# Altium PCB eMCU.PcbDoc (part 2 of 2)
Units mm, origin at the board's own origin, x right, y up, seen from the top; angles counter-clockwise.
Board outline 90 x 58 mm, 2 copper layers (Top Layer, Bottom Layer); 104 components, 112 nets, 449 pads, 70 vias.
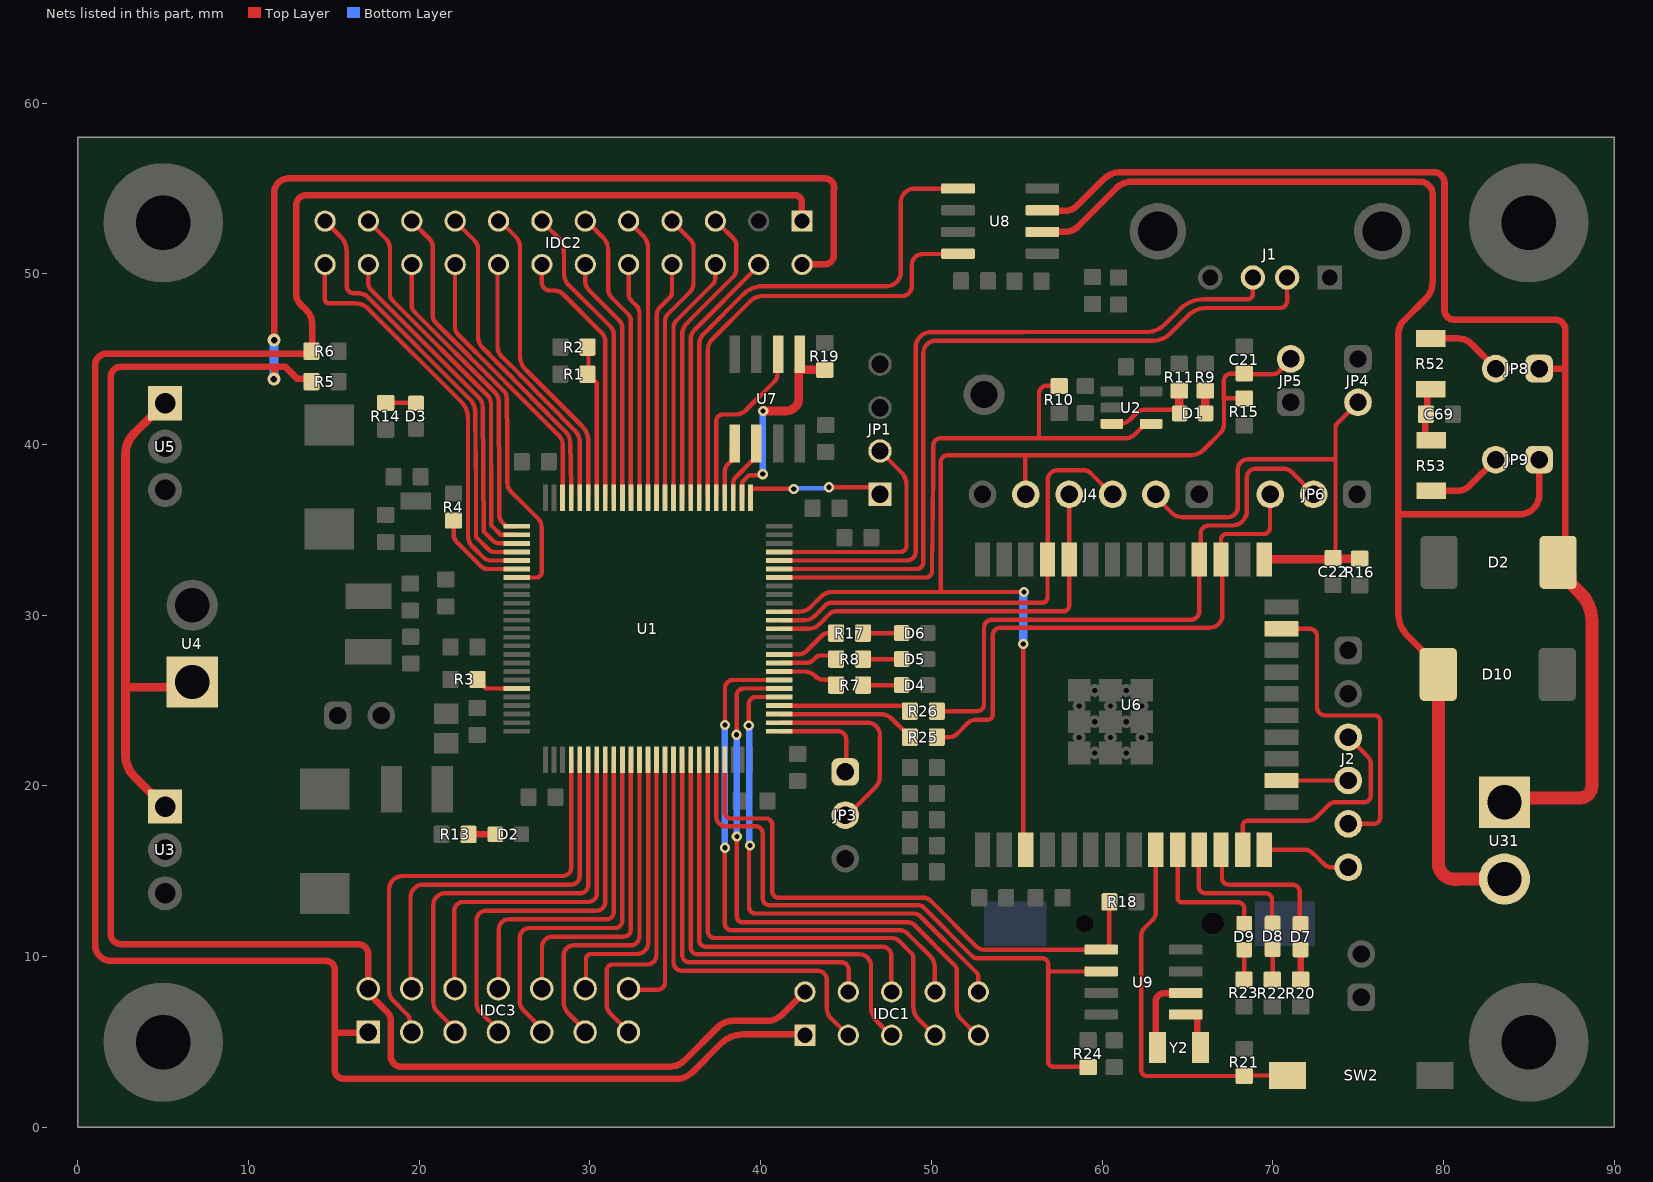
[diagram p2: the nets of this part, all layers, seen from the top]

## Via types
v1: diameter 0.6, hole 0.3, Top Layer to Bottom Layer, tented both sides, 59 vias
v2: diameter 0.762, hole 0.381, Top Layer to Bottom Layer, tented both sides, 11 vias

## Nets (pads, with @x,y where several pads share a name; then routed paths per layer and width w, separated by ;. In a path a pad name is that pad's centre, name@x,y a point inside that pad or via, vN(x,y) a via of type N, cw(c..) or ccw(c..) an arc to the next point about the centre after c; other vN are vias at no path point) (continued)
NetC21_2: C21.2 J4.5 JP5.2 R15.1 U1.65 U6.3 | length 65.8
  Top Layer w0.254: U1.65@41.081,30.21 42.274,30.21 ccw(c42.274,31.132) 42.925,30.479 ; 42.926,30.48 43.532,31.086 cw(c44.196,30.422) 44.196,31.361 50.681,31.361 ; v1(55.384,28.322) 55.384,16.413 U6.3@55.532,16.266 ; v1(55.425,31.361) 50.681,31.361 ; J4.5@55.534,37.084 55.505,37.113 55.505,39.37 ; 65.952,39.695 cw(c65.166,40.481) 65.166,39.37 55.505,39.37 ; 65.953,39.695 66.9,40.642 ccw(c66.331,41.212) 67.136,41.212 67.136,42.71 ; 67.126,42.71 67.126,43.737 cw(c67.538,43.737) 67.538,44.149 68.307,44.149 C21.2@68.326,44.168 68.369,44.125 69.985,44.125 ccw(c69.986,44.681) 70.38,44.288 71.044,44.952 JP5.2@71.044,45.015 ; 67.152,42.71 R15.1@68.316,42.71 ; 50.681,31.361 50.62,31.422 50.546,31.496 50.546,38.971 cw(c50.945,38.971) 50.945,39.37 55.505,39.37
  Bottom Layer w0.508: v1(55.384,28.322) 55.384,31.295 55.425,31.336 v1(55.425,31.361)
NetC22_2: C22.2 J4.2 JP4.2 R16.1 U6.25 | length 29.5
  Top Layer w0.254: J4.2@63.154,37.084 63.154,36.922 64.059,36.017 ccw(c64.714,36.673) 64.714,35.746 67.357,35.746 ccw(c67.357,36.341) 67.952,36.341 67.952,38.552 cw(c68.531,38.552) 68.531,39.13 73.67,39.13 ; U6.25@69.502,33.266 U6.25@69.51,33.274 ; C22.2@73.324,33.274 73.67,33.62 73.67,39.13 ; JP4.2@74.987,42.451 73.865,41.328 ccw(c74.167,40.933) 73.67,40.931 73.67,40.489 73.67,39.13 ; R16.1@75.077,33.315 R16.1@75.083,33.321
  Top Layer w0.508: U6.25@69.51,33.274 C22.2@73.324,33.274 ; C22.2@73.298,33.315 R16.1@75.077,33.315
NetC69_2: C69.2 R52.1 R53.2 | length 3
  Top Layer w0.381: R53.2@78.737,40.206 78.935,40.404 78.935,41.746 C69.2@78.963,41.774 ; C69.2@79.054,42.028 79.054,43.042 R52.1@79.262,43.25
NetD1_A: D1.A R9.1 | length 1.5
  Top Layer w0.508: D1.A@66.04,41.658 R9.1@66.04,43.152
NetD1_C: D1.C R11.1 U2.3 | length 5.6
  Top Layer w0.254: U2.3@60.577,41.214 61.012,41.214 ccw(c61.012,42.123) 61.457,41.331 ccw(c61.012,42.123) 61.636,41.463 ccw(c61.012,42.123) 61.654,41.48 62.007,41.833 cw(c62.521,41.319) 62.521,42.046 ; 62.522,42.046 64.505,42.046 64.547,42.005 D1.C@64.547,41.821
  Top Layer w0.508: D1.C@64.516,42.005 R11.1@64.516,43.152
NetD2_2: D2.2 JP8.1 U8.7 U31.1 | length 74
  Top Layer w0.381: U8.7@56.5,53.721 U8.7@56.545,53.766 ; U8.7@57.276,53.698 57.866,53.698 ccw(c57.866,54.601) 58.482,53.94 ccw(c57.866,54.601) 58.505,53.962 ; 58.504,53.963 60.05,55.509 cw(c61.139,54.42) 61.139,55.96 79.422,55.96 cw(c79.422,55.326) 80.056,55.326 80.056,47.865 ccw(c80.602,47.865) 80.602,47.319 86.542,47.319 cw(c86.542,46.739) 87.122,46.739 87.122,44.45 ; JP8.1@85.598,44.45 87.122,44.45 ; D2.2@86.71,33.095 87.122,33.507 87.122,44.45
  Top Layer w0.762: U31.1@83.566,19.05 83.82,19.304 88.011,19.304 ccw(c88.011,19.976) 88.683,19.976 88.683,29.691 ccw(c86.431,29.691) 88.024,31.282 ; D2.2@86.71,33.095 87.419,32.386 87.419,31.888 88.023,31.283
NetD2_A: D2.A R13.1 | length 1.6
  Top Layer w0.381: R13.1@22.892,17.162 24.402,17.162 D2.A@24.47,17.094
NetD3_A: D3.A R14.1 | length 2.1
  Top Layer w0.254: R14.1@18.034,42.446 D3.A@20.094,42.446
NetD4_A: D4.A R7.1 | length 2.8
  Top Layer w0.254: R7.1@46.002,25.908 D4.A@48.514,25.908 ; D4.A@48.26,25.908 D4.A@48.26,26.162
NetD5_A: D5.A R8.1 | length 3
  Top Layer w0.254: R8.1@46.171,27.601 R8.1@46.002,27.432 D5.A@48.514,27.432 ; D5.A@48.119,27.686 D5.A@48.288,27.517
NetD6_A: D6.A R17.1 | length 2.8
  Top Layer w0.254: R17.1@46.002,28.956 D6.A@48.514,28.956 ; D6.A@48.26,28.956 D6.A@48.26,29.21
NetD7_A: D7.A R20.1 | length 1.7
  Top Layer w0.381: R20.1@71.628,8.664 D7.A@71.628,10.414
NetD7_C: D7.C U6.12 | length 8.6
  Top Layer w0.254: U6.12@66.962,16.266 67.02,16.207 67.02,14.604 ccw(c67.4,14.604) 67.4,14.224 71.133,14.224 cw(c71.133,13.769) 71.579,13.859 cw(c71.133,13.769) 71.588,13.769 71.588,13.708 ; 71.579,13.708 71.579,11.983 D7.C@71.628,11.934
NetD8_A: D8.A R22.1 | length 1.8
  Top Layer w0.254: R22.1@69.967,8.66 69.989,8.682 D8.A@69.989,10.433
NetD8_C: D8.C U6.11 | length 8.3
  Top Layer w0.254: U6.11@65.692,16.266 65.666,16.24 65.666,14.097 ccw(c66.047,14.097) 66.047,13.716 69.596,13.716 cw(c69.596,13.364) 69.948,13.364 69.948,13.259 ; 69.951,13.259 69.951,11.991 D8.C@69.989,11.953
NetD9_A: D9.A R23.1 | length 1.8
  Top Layer w0.254: R23.1@68.312,8.667 68.326,8.681 D9.A@68.326,10.416
NetD9_C: D9.C U6.10 | length 8
  Top Layer w0.254: U6.10@64.422,16.266 64.422,13.455 ccw(c64.688,13.455) 64.688,13.188 ; 64.688,13.183 67.97,13.183 cw(c67.97,12.827) 68.326,12.827 D9.C@68.326,11.936
NetD10_2: D10.2 JP9.1 U8.6 U31.2 | length 80.1
  Top Layer w0.381: U8.6@56.5,52.451 57.805,52.451 ccw(c57.805,53.578) 58.521,52.708 ccw(c57.805,53.578) 58.602,52.781 ; 58.598,52.785 60.831,55.018 ; 60.83,55.02 cw(c61.751,54.099) 60.881,55.067 cw(c61.751,54.099) 61.751,55.401 78.605,55.401 cw(c78.605,54.643) 79.361,54.696 cw(c78.605,54.643) 79.363,54.643 ; 77.35,46.427 77.35,35.907 ; 77.359,46.427 77.359,46.512 cw(c78.399,46.512) 77.663,47.248 78.972,48.556 ccw(c78.034,49.494) 79.361,49.494 79.361,54.643 ; D10.2@79.692,27.003 77.891,28.804 77.889,28.806 cw(c79.19,30.107) 77.35,30.107 77.35,30.108 77.35,35.907 ; JP9.1@85.613,38.608 85.613,37.086 cw(c84.434,37.086) 84.434,35.907 77.35,35.907
  Top Layer w0.635: D10.2@79.692,26.533 D10.2@79.692,27.003
  Top Layer w0.762: D10.2@79.692,26.533 79.692,15.494 ccw(c80.648,15.494) 80.495,14.55 ccw(c80.648,15.494) 80.648,14.538 80.862,14.538 ; 80.862,14.55 U31.2@83.566,14.55
NetIDC1_1: IDC1.1 IDC2.1 IDC3.1 R6.2 | length 138.4
  Top Layer w0.381: 13.024,48.235 13.444,47.816 ; 13.026,48.237 cw(c13.58,48.791) 12.797,48.791 12.797,54.013 cw(c13.394,54.013) 13.394,54.61 41.987,54.61 cw(c41.987,54.179) 42.418,54.179 IDC2.1@42.418,53.086 ; 13.444,47.816 cw(c12.78,47.153) 13.718,47.153 13.718,47.122 ; R6.2@13.688,45.466 13.537,45.315 1.678,45.315 ccw(c1.678,44.654) 1.016,44.654 1.016,10.702 ccw(c1.965,10.702) 1.965,9.753 14.546,9.753 cw(c14.546,9.247) 15.052,9.247 ; R6.2@13.688,45.72 13.725,45.757 13.725,47.122 ; 15.061,9.247 15.061,5.545 ; 15.572,2.845 35.036,2.845 ccw(c35.036,4.232) 36.017,3.251 37.669,4.903 cw(c39.001,3.572) 39.001,5.455 42.412,5.455 IDC1.1@42.472,5.394 ; 15.572,2.849 cw(c15.572,3.359) 15.061,3.359 15.061,5.545 ; IDC3.1@17.018,5.588 16.975,5.545 15.061,5.545
NetIDC1_2: IDC1.2 IDC2.2 IDC3.2 R5.2 | length 144.3
  Top Layer w0.381: v2(11.493,43.827) 11.523,43.857 11.523,44.325 ; v2(11.502,46.12) 11.514,46.132 11.514,54.708 ccw(c11.133,54.708) 11.514,54.724 cw(c12.337,54.763) 12.337,55.587 43.764,55.587 cw(c43.764,55.041) 44.296,54.916 44.296,51.105 cw(c43.915,51.105) 44.294,51.075 cw(c43.722,51.121) 43.72,50.546 IDC2.2@42.672,50.546 ; 12.119,44.551 12.119,44.548 11.74,44.548 2.526,44.548 ccw(c2.526,43.955) 1.933,43.955 1.933,11.328 ccw(c2.516,11.328) 2.516,10.744 16.408,10.744 cw(c16.408,10.134) 17.018,10.131 IDC3.2@17.018,8.128 ; 12.165,44.546 12.87,43.841 13.535,43.841 R5.2@13.688,43.688 ; IDC3.2@17.207,8.063 17.207,7.683 18.132,6.759 cw(c17.626,6.253) 18.338,6.324 cw(c17.626,6.253) 18.341,6.253 ; 18.338,6.253 18.338,4.169 ccw(c18.95,4.169) 18.95,3.556 34.671,3.556 ccw(c34.671,4.77) 35.529,3.912 ; 35.531,3.909 37.531,5.909 ; 37.535,5.905 cw(c38.339,5.101) 38.339,6.238 40.346,6.238 ccw(c40.346,7.553) 41.277,6.624 IDC1.2@42.596,7.943
  Bottom Layer w0.508: v2(11.493,43.827) 11.497,43.831 11.497,46.115 v2(11.502,46.12)
NetIDC1_3: IDC1.3 U1.41 | length 24.8
  Top Layer w0.254: U1.41@34.901,21.423 34.901,9.643 ccw(c35.358,9.643) 35.358,9.186 43.324,9.186 cw(c43.324,8.635) 43.874,8.635 43.874,6.981 ccw(c44.683,6.981) 44.058,6.468 ccw(c44.683,6.981) 44.111,6.409 ; 44.124,6.402 IDC1.3@44.938,5.588
NetIDC1_4: IDC1.4 U1.42 | length 23
  Top Layer w0.254: U1.42@35.401,21.53 35.401,10.109 ccw(c35.833,10.109) 35.833,9.678 44.724,9.678 cw(c44.724,9.248) 45.154,9.248 IDC1.4@45.154,7.96
NetIDC1_5: IDC1.5 U1.43 | length 26.4
  Top Layer w0.254: U1.43@35.903,21.528 35.903,10.536 ccw(c36.299,10.536) 36.299,10.141 45.785,10.141 cw(c45.785,9.459) 46.467,9.459 46.467,7.102 ; 46.467,7.101 ccw(c47.786,7.101) 46.854,6.167 47.433,5.588 IDC1.5@47.498,5.588
NetIDC1_6: IDC1.6 U1.44 | length 24.4
  Top Layer w0.254: U1.44@36.401,21.53 36.401,11.044 cw(c36.147,11.044) 36.4,11.018 ccw(c36.788,10.976) 36.789,10.586 47.11,10.586 cw(c47.11,10.038) 47.659,10.038 IDC1.6@47.659,7.96
NetIDC1_7: IDC1.7 U1.45 | length 27.8
  Top Layer w0.254: U1.45@36.901,21.53 36.901,11.5 ccw(c37.304,11.5) 37.304,11.096 47.675,11.096 cw(c47.675,10.458) 48.124,10.911 cw(c47.675,10.458) 48.126,10.909 48.84,10.195 cw(c48.587,9.943) 48.944,9.943 ; 48.946,7.068 ccw(c50,7.068) 49.256,6.322 49.502,6.075 50.092,5.485 IDC1.7@50.092,5.394 ; 48.946,7.07 48.946,9.943
NetIDC1_8: IDC1.8 U1.57 | length 32.3
  Top Layer w0.254: 37.902,11.949 ccw(c38.305,11.949) 38.356,11.548 cw(c38.387,11.296) 38.387,11.55 48.123,11.55 cw(c48.123,10.851) 48.618,11.346 48.628,11.335 ; 37.902,11.95 37.902,16.378 v1(37.908,16.384) ; v1(37.913,23.578) 37.91,23.581 37.91,25.671 ccw(c37.656,25.671) 37.91,25.689 cw(c38.391,25.727) 38.391,26.21 U1.57@41.081,26.21 ; 48.631,11.338 49.931,10.038 ; 49.931,10.037 cw(c49.296,9.4) 50.196,9.4 50.196,7.963 IDC1.8@50.216,7.943
  Bottom Layer w0.254: v1(37.908,16.384) v1@37.911,16.387 ; v1@37.911,23.576 v1(37.913,23.578)
  Bottom Layer w0.381: v1@37.911,16.387 v1@37.911,23.576
NetIDC1_9: IDC1.9 U1.56 | length 34.2
  Top Layer w0.254: v1(38.593,23.001) 38.593,25.209 ccw(c38.339,25.209) 38.591,25.239 cw(c39.008,25.29) 39.008,25.71 U1.56@41.081,25.71 ; v1(38.608,17.04) 38.608,12.335 ccw(c38.92,12.335) 38.92,12.023 48.609,12.023 cw(c48.609,11.48) 48.994,11.864 ; 48.997,11.868 51.375,9.49 cw(c51.087,9.202) 51.494,9.226 51.494,6.891 ; 51.494,6.89 ccw(c52.215,6.89) 51.706,6.38 ; 51.706,6.379 52.632,5.453 IDC1.9@52.632,5.394
  Bottom Layer w0.254: v1(38.593,23.001) v1@38.6,22.994 ; v1@38.6,17.048 v1(38.608,17.04)
  Bottom Layer w0.381: v1@38.6,17.048 v1@38.6,22.994
NetIDC1_10: IDC1.10 U1.55 | length 30
  Top Layer w0.254: v1(39.305,23.541) 39.305,24.782 ccw(c39.051,24.782) 39.305,24.789 cw(c39.712,24.803) 39.712,25.21 U1.55@41.081,25.21 ; v1(39.37,16.51) 39.32,16.46 39.32,12.904 ccw(c39.689,12.902) 39.691,12.533 48.968,12.533 cw(c48.969,12.002) 49.345,12.377 52.359,9.363 52.643,9.079 cw(c52.404,8.838) 52.744,8.838 IDC1.10@52.744,7.955
  Bottom Layer w0.254: v1(39.305,23.541) v1@39.337,23.508 ; v1@39.337,16.543 v1(39.37,16.51)
  Bottom Layer w0.381: v1@39.337,16.543 v1@39.337,23.508
NetIDC2_4: IDC2.4 U1.83 | length 15.1
  Top Layer w0.254: U1.83@35.901,36.89 35.901,46.08 ccw(c35.647,46.08) 35.901,46.095 cw(c36.716,46.149) 36.139,46.727 39.703,50.292 IDC2.4@39.87,50.292
NetIDC2_5: IDC2.5 U1.84 | length 17.8
  Top Layer w0.254: U1.84@35.401,36.89 35.401,46.362 ccw(c35.147,46.362) 35.401,46.372 cw(c36.398,46.416) 35.692,47.122 38.381,49.811 ccw(c37.916,50.277) 38.575,50.277 38.575,51.646 38.575,51.689 ccw(c38.067,51.689) 38.575,51.706 ccw(c38.067,51.689) 38.426,52.048 37.592,52.882 IDC2.5@37.592,53.086
NetIDC2_6: IDC2.6 U1.85 | length 14.6
  Top Layer w0.254: U1.85@34.901,36.89 34.901,37.543 34.901,46.882 cw(c35.41,46.882) 35.05,47.242 37.205,49.397 ccw(c36.889,49.713) 37.336,49.713 ; 37.338,49.713 IDC2.6@37.338,50.546
NetIDC2_7: IDC2.7 U1.86 | length 17.2
  Top Layer w0.254: U1.86@34.401,36.89 34.402,47.27 ; 34.403,47.27 cw(c34.888,47.27) 34.544,47.613 ; 34.545,47.613 35.838,48.907 ccw(c35.285,49.461) 36.068,49.461 ; IDC2.7@34.883,53.001 35.887,51.997 ; 35.887,51.997 cw(c35.449,51.558) 36.068,51.522 ccw(c36.322,51.509) 36.068,51.51 36.068,49.462
NetIDC2_8: IDC2.8 U1.87 | length 14
  Top Layer w0.254: U1.87@33.901,36.89 33.914,36.903 33.914,37.638 33.921,37.645 33.921,47.617 ; 33.921,47.618 cw(c34.495,47.618) 34.089,48.023 34.673,48.607 ccw(c34.346,48.934) 34.808,48.934 IDC2.8@34.808,50.546
NetIDC2_9: IDC2.9 U1.88 | length 16.6
  Top Layer w0.254: IDC2.9@32.258,53.086 33.115,52.229 cw(c32.429,51.543) 33.399,51.543 ; U1.88@33.401,36.89 33.401,51.543
NetIDC2_10: IDC2.10 U1.89 | length 13.9
  Top Layer w0.254: IDC2.10@32.268,50.546 32.268,48.79 ccw(c32.758,48.79) 32.412,48.444 32.708,48.148 32.74,48.116 cw(c32.35,47.726) 32.901,47.742 cw(c32.35,47.726) 32.901,47.726 U1.89@32.901,36.89
NetIDC2_11: IDC2.11 U1.90 | length 17.1
  Top Layer w0.254: IDC2.11@29.972,53.086 29.972,52.929 30.757,52.143 ; 30.758,52.142 cw(c30.006,51.39) 31.068,51.332 ccw(c31.322,51.32) 31.068,51.321 31.068,49.137 ccw(c31.863,49.137) 31.301,48.575 32.232,47.644 cw(c31.821,47.234) 32.401,47.261 cw(c31.821,47.234) 32.402,47.234 U1.90@32.401,36.89
NetIDC2_12: IDC2.12 U1.91 | length 14.5
  Top Layer w0.254: IDC2.12@29.728,50.546 29.728,49.579 ccw(c30.486,49.579) 29.932,49.062 ccw(c30.486,49.579) 29.95,49.043 ; 29.951,49.043 31.692,47.302 cw(c31.189,46.799) 31.9,46.799 31.9,46.772 ; U1.91@31.901,36.89 31.901,46.772 31.903,46.771
NetIDC2_13: IDC2.13 U1.92 | length 17.7
  Top Layer w0.254: IDC2.13@27.432,53.086 27.432,52.832 28.2,52.064 cw(c27.543,51.401) 28.476,51.4 28.476,51.188 ; 28.485,51.188 28.485,50.021 ccw(c29.458,50.021) 28.71,49.398 ccw(c29.458,50.021) 28.77,49.332 ; 28.773,49.335 31.227,46.881 ; 31.228,46.88 cw(c30.813,46.464) 31.401,46.464 ; U1.92@31.401,36.89 31.401,46.463
NetIDC2_14: IDC2.14 U1.93 | length 15.1
  Top Layer w0.254: IDC2.14@27.178,50.292 27.188,50.282 27.188,49.492 ccw(c27.659,49.492) 27.628,49.023 ; 27.686,49.023 27.901,49.023 cw(c27.901,48.286) 28.422,48.807 ; 28.492,48.742 30.694,46.54 cw(c30.188,46.03) 30.899,46.133 cw(c30.647,46.098) 30.901,46.098 U1.93@30.901,36.89
NetIDC2_15: IDC2.15 U1.95 | length 18.3
  Top Layer w0.254: IDC2.15@24.638,53.086 24.742,53.086 25.64,52.188 cw(c25,51.548) 25.905,51.548 ; 25.908,51.548 25.908,45.195 25.908,45.193 ccw(c27.089,45.193) 26.264,44.348 cw(c26.086,44.167) 26.266,44.346 29.546,41.066 cw(c28.701,40.211) 29.901,40.153 ccw(c30.155,40.142) 29.901,40.143 ; U1.95@29.901,36.89 29.901,37.543 29.901,40.142
NetIDC2_16: IDC2.16 U1.96 | length 15.6
  Top Layer w0.254: 24.586,46.385 24.586,50.494 IDC2.16@24.638,50.546 ; 24.589,45.738 ccw(c25.416,45.738) 24.932,45.068 24.944,45.056 ; 24.589,45.739 24.589,46.385 ; 24.945,45.055 25.814,44.186 25.844,44.156 25.844,44.151 29.136,40.8 29.138,40.797 cw(c28.495,40.158) 29.401,40.118 ccw(c29.655,40.108) 29.401,40.11 ; U1.96@29.401,36.89 29.401,37.543 29.401,40.108
NetIDC2_17: IDC2.17 U1.97 | length 18.9
  Top Layer w0.254: IDC2.17@22.098,53.086 23.234,51.95 cw(c22.717,51.433) 23.446,51.496 23.446,46.316 ccw(c24.348,46.316) 23.69,45.699 24.519,44.856 ccw(c25.416,45.738) 24.521,44.854 28.585,40.74 cw(c27.956,40.111) 28.846,40.113 cw(c27.956,40.111) 28.846,40.111 28.9,37.543 U1.97@28.913,36.903
NetIDC2_18: IDC2.18 U1.98 | length 16.2
  Top Layer w0.254: 22.098,46.874 ccw(c22.725,46.874) 22.282,46.43 ; 22.098,46.875 IDC2.18@22.098,50.546 ; 22.283,46.429 24.466,44.246 25.557,43.155 28.103,40.604 cw(c27.601,39.979) 28.403,39.979 U1.98@28.403,36.892
NetIDC2_19: IDC2.19 U1.7 | length 25.2
  Top Layer w0.254: IDC2.19@19.558,53.086 20.59,52.054 ; 20.591,52.056 cw(c20.095,51.559) 20.629,52.015 cw(c20.095,51.559) 20.797,51.559 20.797,47.542 20.797,47.54 ccw(c21.366,47.54) 20.965,47.137 20.966,47.135 24.957,43.144 cw(c24.552,42.739) 25.125,42.739 25.125,42.586 ; 25.125,42.563 25.162,40.48 25.162,37.754 25.162,37.753 ccw(c25.865,37.753) 25.367,37.256 25.369,37.254 26.195,36.429 26.958,35.665 cw(c26.426,35.134) 27.178,35.148 cw(c26.426,35.134) 27.178,35.134 27.178,35.116 27.178,32.533 cw(c26.857,32.533) 26.857,32.212 U1.7@25.723,32.212
NetIDC2_20: IDC2.20 U1.1 | length 18.2
  Top Layer w0.254: 19.558,48.173 ccw(c20.138,48.173) 19.731,47.759 24.423,43.068 ; 19.558,48.174 IDC2.20@19.558,50.546 ; 24.423,43.067 cw(c23.862,42.505) 24.655,42.454 ccw(c24.909,42.439) 24.655,42.44 ; 24.655,42.439 24.655,42.309 24.655,42.307 24.69,37.398 24.69,35.893 ccw(c25.346,35.892) 24.883,35.427 25.068,35.242 25.068,35.223 25.081,35.21 U1.1@25.721,35.21
NetIDC2_21: IDC2.21 U1.2 | length 22.4
  Top Layer w0.254: IDC2.21@17.018,53.086 18.034,52.07 cw(c17.421,51.457) 18.288,51.457 18.288,48.814 ccw(c18.823,48.814) 18.446,48.434 23.989,42.891 cw(c23.461,42.36) 23.99,42.89 cw(c23.461,42.36) 24.21,42.354 ; 24.21,42.353 24.218,35.274 24.292,35.2 24.778,34.714 25.244,34.714 25.248,34.71 U1.2@25.721,34.71
NetIDC2_22: IDC2.22 U1.3 | length 20.3
  Top Layer w0.254: IDC2.22@17.018,50.292 17.018,49.449 ccw(c17.56,49.449) 17.147,49.098 ccw(c17.56,49.449) 17.177,49.066 ; 17.178,49.067 23.213,43.033 23.492,42.753 ; 23.493,42.752 cw(c22.938,42.199) 23.722,42.202 cw(c22.938,42.199) 23.722,42.199 23.722,42.191 23.729,42.118 ; 23.729,42.117 23.785,34.904 23.859,34.83 24.247,34.442 24.248,34.444 24.273,34.419 24.339,34.353 ccw(c24.673,34.688) 24.673,34.215 U1.3@25.716,34.215
NetIDC2_23: IDC2.23 U1.4 | length 25.2
  Top Layer w0.254: IDC2.23@14.486,53.086 15.401,52.171 cw(c14.562,51.332) 15.748,51.332 15.748,49.276 ccw(c16.172,49.276) 16.172,48.852 16.47,48.852 ; 16.47,48.853 cw(c16.47,48.133) 16.509,48.852 cw(c16.47,48.133) 16.979,48.643 ; 16.979,48.642 17.082,48.54 22.893,42.729 22.899,42.722 cw(c22.16,41.866) 23.292,41.866 23.329,37.358 cw(c23.075,37.356) 23.329,37.356 23.329,34.583 24.074,33.838 ccw(c24.382,34.145) 24.382,33.71 U1.4@25.721,33.71
NetIDC2_24: IDC2.24 U1.5 | length 23.8
  Top Layer w0.254: 14.469,48.514 IDC2.24@14.469,50.301 ; 14.478,48.514 ccw(c14.725,48.514) 14.725,48.267 16.284,48.267 ; 16.285,48.267 cw(c16.285,47.268) 16.992,47.974 ; 16.993,47.973 22.445,42.521 22.448,42.521 cw(c21.459,41.528) 22.86,41.471 22.86,34.651 ccw(c23.721,34.651) 23.113,34.041 23.229,33.926 ; 23.226,33.924 23.794,33.356 ccw(c24.147,33.71) 24.147,33.21 U1.5@25.721,33.21
NetIDC3_3: IDC3.3 U1.29 | length 26.6
  Top Layer w0.254: 19.439,6.29 19.439,5.707 IDC3.3@19.558,5.588 ; 19.44,6.29 ccw(c19.009,6.29) 19.439,6.313 ccw(c19.009,6.29) 19.314,6.594 18.461,7.447 cw(c19.011,7.998) 18.233,7.998 18.233,13.928 cw(c19.037,13.928) 19.037,14.732 28.421,14.732 ccw(c28.421,15.212) 28.901,15.212 U1.29@28.901,21.53
NetIDC3_4: IDC3.4 U1.30 | length 22.8
  Top Layer w0.254: IDC3.4@19.558,8.128 19.495,8.191 19.495,13.441 ccw(c19.241,13.441) 19.495,13.45 cw(c20.238,13.48) 20.238,14.224 28.894,14.224 ccw(c28.894,14.731) 29.401,14.731 U1.30@29.401,21.53
NetIDC3_5: IDC3.5 U1.31 | length 25
  Top Layer w0.254: 20.829,7.331 ccw(c21.589,7.331) 21.053,6.793 ; 20.829,7.332 20.829,13.031 cw(c21.514,13.031) 21.514,13.716 29.409,13.716 ccw(c29.409,14.208) 29.901,14.208 U1.31@29.901,21.53 ; 21.053,6.792 22.098,5.747 IDC3.5@22.098,5.588
NetIDC3_6: IDC3.6 U1.32 | length 21.3
  Top Layer w0.254: IDC3.6@22.098,8.128 22.055,8.171 22.055,12.687 cw(c22.577,12.687) 22.577,13.208 29.911,13.208 ccw(c29.911,13.698) 30.4,13.698 U1.32@30.401,21.53
NetIDC3_7: IDC3.7 U1.33 | length 23.5
  Top Layer w0.254: 23.354,7.261 ccw(c24.023,7.261) 23.551,6.787 24.638,5.7 IDC3.7@24.638,5.588 ; 23.354,7.262 23.354,12.123 cw(c23.931,12.123) 23.931,12.7 30.39,12.7 ccw(c30.39,13.211) 30.901,13.211 U1.33@30.901,21.53
NetIDC3_8: IDC3.8 U1.34 | length 19.7
  Top Layer w0.254: IDC3.8@24.638,8.128 24.67,8.16 24.67,11.613 cw(c25.249,11.613) 25.249,12.192 30.987,12.192 ccw(c30.987,12.606) 31.401,12.606 U1.34@31.401,21.53
NetIDC3_9: IDC3.9 U1.35 | length 22
  Top Layer w0.254: 25.887,7.412 ccw(c26.664,7.412) 26.116,6.862 27.178,5.8 IDC3.9@27.178,5.588 ; 25.887,7.413 25.887,11.092 cw(c26.479,11.092) 26.479,11.684 31.469,11.684 ccw(c31.469,12.116) 31.901,12.116 U1.35@31.901,21.53
NetIDC3_10: IDC3.10 U1.36 | length 18.2
  Top Layer w0.254: IDC3.10@27.178,8.128 27.199,8.149 27.199,10.581 cw(c27.794,10.581) 27.794,11.176 31.984,11.176 ccw(c31.984,11.593) 32.401,11.593 U1.36@32.401,21.53
NetIDC3_11: IDC3.11 U1.37 | length 20.4
  Top Layer w0.254: 28.466,7.338 ccw(c29.383,7.338) 28.735,6.689 ; 28.466,7.339 28.466,10.088 cw(c29.046,10.088) 29.046,10.668 32.382,10.668 ccw(c32.382,11.187) 32.901,11.187 U1.37@32.901,21.53 ; 28.736,6.688 29.718,5.706 IDC3.11@29.718,5.588
NetIDC3_12: IDC3.12 U1.38 | length 16.6
  Top Layer w0.254: IDC3.12@29.718,8.128 29.772,8.182 29.772,9.851 cw(c30.08,9.851) 30.08,10.16 32.766,10.16 ccw(c32.766,10.802) 33.408,10.802 U1.38@33.408,21.523
NetIDC3_13: IDC3.13 U1.39 | length 19
  Top Layer w0.254: 30.988,7.153 ccw(c31.638,7.153) 31.179,6.693 32.258,5.614 IDC3.13@32.258,5.588 ; 30.988,7.154 30.988,9.195 cw(c31.339,9.195) 31.339,9.546 33.337,9.546 ; 33.337,9.542 ccw(c33.337,10.106) 33.408,9.546 ccw(c33.337,10.106) 33.901,10.106 U1.39@33.901,21.53
NetIDC3_14: IDC3.14 U1.40 | length 15.5
  Top Layer w0.254: IDC3.14@31.75,8.382 IDC3.14@31.775,8.357 ; IDC3.14@32.258,8.128 32.32,8.066 33.958,8.066 ccw(c33.958,8.509) 34.401,8.509 U1.40@34.401,21.53
NetJ1_2: J1.2 U1.70 | length 44.4
  Top Layer w0.254: U1.70@41.081,32.71 49.123,32.71 ccw(c49.123,33.117) 49.53,33.117 49.53,45.356 cw(c50.254,45.356) 50.254,46.081 62.989,46.081 ccw(c62.99,47.477) 63.979,46.49 65.04,47.552 cw(c66.119,46.478) 66.119,48 ; 66.12,48 70.425,48 ccw(c70.425,48.413) 70.838,48.413 70.838,48.764 70.834,48.768 J1.2@70.834,49.276
NetJ1_3: J1.3 U1.71 | length 41.8
  Top Layer w0.254: U1.71@41.081,33.21 48.579,33.21 ccw(c48.579,33.707) 49.076,33.707 49.076,45.681 cw(c49.976,45.681) 49.976,46.581 55.438,46.581 ; 55.447,46.589 62.583,46.589 ccw(c62.583,48.152) 63.688,47.047 ; 63.69,47.045 64.443,47.798 cw(c65.956,46.545) 65.956,48.509 68.517,48.509 ccw(c68.517,48.827) 68.834,48.827 J1.3@68.834,49.276
NetJ2_3: J2.3 U6.13 | length 13.5
  Top Layer w0.254: U6.13@68.232,16.266 68.232,17.669 ; 68.239,17.669 cw(c68.537,17.669) 68.537,17.967 72.037,17.967 ccw(c72.037,18.727) 72.575,18.19 ; 72.578,18.186 73.291,18.899 ; 73.295,18.895 73.301,18.901 cw(c73.66,18.542) 73.66,19.05 75.362,19.05 ccw(c75.362,19.421) 75.733,19.421 75.733,21.309 ; J2.3@74.676,22.86 74.676,22.606 75.568,21.714 ; 75.568,21.714 cw(c75.162,21.309) 75.733,21.362 cw(c75.162,21.309) 75.736,21.309
NetJ2_4: J2.4 U6.16 | length 3.9
  Top Layer w0.254: U6.16@70.502,20.321 J2.4@74.422,20.32
NetJ2_5: J2.5 U6.23 | length 17.8
  Top Layer w0.254: U6.23@71.12,29.21 72.167,29.21 cw(c72.167,28.794) 72.583,28.794 72.583,24.623 ccw(c73.073,24.623) 73.073,24.133 75.974,24.133 cw(c75.974,23.822) 76.286,23.822 ; J2.5@74.422,17.78 75.903,17.78 ccw(c75.903,18.165) 76.287,18.165 76.287,23.822
NetJ2_6: J2.6 U6.14 | length 5.3
  Top Layer w0.254: U6.14@69.502,16.266 71.82,16.266 cw(c71.82,15.486) 72.372,16.037 72.401,16.008 ; 72.407,16.014 72.927,15.494 ; 72.931,15.498 73.016,15.412 ccw(c73.432,15.828) 73.432,15.24 J2.6@74.422,15.24
NetJ4_3: J4.3 U1.64 U6.35 | length 27.8
  Top Layer w0.254: U1.64@41.081,29.71 42.547,29.71 ccw(c42.547,30.605) 43.18,29.972 43.815,30.607 cw(c44.122,30.3) 44.122,30.734 56.494,30.734 ccw(c56.494,31.038) 56.799,31.038 ; 56.802,31.038 U6.35@56.802,33.266 56.809,33.273 56.809,37.909 cw(c57.399,37.909) 57.399,38.499 58.912,38.499 cw(c58.912,37.91) 59.303,38.35 cw(c58.912,37.91) 59.328,38.326 ; 59.327,38.326 60.569,37.084 J4.3@60.614,37.084
NetJ4_4: J4.4 U1.63 U6.34 | length 24
  Top Layer w0.254: U1.63@41.091,29.21 42.821,29.21 ccw(c42.821,30.077) 43.433,29.463 44.069,30.099 cw(c44.376,29.792) 44.376,30.226 57.723,30.226 ccw(c57.723,30.57) 58.067,30.57 ; 58.072,30.57 U6.34@58.072,33.266 ; U6.34@58.074,33.268 J4.4@58.074,37.084
NetJP1_1: JP1.1 U1.76 | length 8
  Top Layer w0.254: U1.76@39.401,36.89 39.401,37.394 39.414,37.407 v1@41.923,37.407 ; v1(44.003,37.496) 46.736,37.496 JP1.1@46.736,37.338
  Bottom Layer w0.254: v1(41.939,37.39) 41.993,37.443 43.95,37.443 v1(44.003,37.496)
NetJP1_2: JP1.2 U1.72 | length 13.8
  Top Layer w0.254: U1.72@41.081,33.71 44.631,33.71 44.634,33.707 48.184,33.707 ccw(c48.184,34.067) 48.543,34.067 48.543,37.657 ccw(c47.549,37.659) 48.252,38.362 ; JP1.2@46.99,39.624 48.251,38.363
NetJP3_1: JP3.1 U1.51 | length 6.1
  Top Layer w0.254: U1.51@41.081,23.21 44.52,23.21 cw(c44.52,22.71) 45.02,22.71 45.02,20.89 JP3.1@44.958,20.828
NetJP3_2: JP3.2 U1.52 | length 11.9
  Top Layer w0.254: U1.52@41.081,23.71 46.254,23.712 cw(c46.254,22.978) 46.982,22.886 46.982,20.632 ; JP3.2@44.958,18.288 45.082,18.288 46.71,19.916 ccw(c46.043,20.583) 46.985,20.632
NetJP6_2: JP6.2 R26.1 U6.28 | length 34.9
  Top Layer w0.254: 50.828,24.384 52.68,24.384 ccw(c52.68,24.79) 53.086,24.79 53.086,29.276 cw(c53.547,29.276) 53.547,29.737 65.184,29.737 ccw(c65.184,30.245) 65.692,30.245 U6.28@65.692,33.266 65.773,33.346 65.773,34.787 cw(c66.239,34.787) 66.239,35.254 67.602,35.254 ccw(c67.602,36.133) 68.481,36.133 68.481,38.074 68.481,38.076 cw(c68.995,38.076) 69.015,38.59 ccw(c69.022,38.844) 69.02,38.59 70.59,38.59 cw(c70.591,37.826) 71.131,38.366 71.132,38.365 JP6.2@72.39,37.107
NetJP6_3: JP6.3 R25.1 U6.27 | length 32
  Top Layer w0.254: R25.1@50.546,22.86 51.039,22.86 ccw(c51.039,23.513) 51.471,23.023 ccw(c51.039,23.513) 51.501,23.051 51.528,23.078 ; 51.527,23.079 52.133,23.685 ; 52.13,23.687 cw(c52.585,23.232) 52.184,23.736 cw(c52.585,23.232) 52.585,23.876 53.285,23.876 ccw(c53.285,24.182) 53.591,24.182 53.591,24.258 ; 53.594,24.258 53.594,28.814 cw(c54.057,28.814) 54.057,29.278 66.319,29.278 ccw(c66.319,29.999) 67.04,29.999 67.04,33.187 U6.27@66.962,33.266 66.962,34.429 cw(c67.298,34.429) 67.298,34.765 69.457,34.765 ccw(c69.457,35.141) 69.833,35.141 JP6.3@69.833,37.067
NetJP8_2: JP8.2 R52.2 | length 3.8
  Top Layer w0.381: R52.2@79.979,46.215 80.832,46.215 80.834,46.215 cw(c80.836,45.068) 81.662,45.863 ccw(c81.936,46.129) 81.665,45.861 81.666,45.859 JP8.2@83.058,44.467
NetJP9_2: JP9.2 R53.1 | length 4.5
  Top Layer w0.381: R53.1@79.275,37.281 80.784,37.281 ccw(c80.784,38.342) 81.457,37.522 ccw(c80.784,38.342) 81.534,37.592 ; 81.53,37.596 JP9.2@83.051,39.116
NetR1_1: R1.1 R2.2 U1.94 | length 9
  Top Layer w0.254: R1.1@29.854,44.12 29.915,44.181 29.915,45.651 R2.2@29.858,45.708 ; R1.1@29.966,44.04 30.395,43.611 U1.94@30.395,36.896
NetR3_2: R3.2 U1.20 | length 2.4
  Top Layer w0.254: R3.2@23.531,26.086 R3.2@23.84,25.777 ; U1.20@25.721,25.71 25.717,25.714 23.991,25.714 cw(c23.991,25.929) R3.2@23.851,25.766 ; R3.2@23.839,25.777 ccw(c23.991,25.929) R3.2@23.851,25.766 ; R3.2@23.84,25.777 R3.2@23.851,25.766
NetR4_2: R4.2 U1.6 | length 5.4
  Top Layer w0.254: R4.2@22.024,35.533 22.024,34.724 ccw(c22.635,34.724) 22.203,34.292 22.318,34.177 ; 22.317,34.176 23.583,32.91 ; 23.589,32.916 23.658,32.847 ccw(c23.989,33.179) 23.989,32.71 U1.6@25.721,32.71
NetR7_2: R7.2 U1.58 | length 3.6
  Top Layer w0.254: U1.58@41.081,26.71 42.533,26.71 cw(c42.535,25.749) 43.167,26.472 cw(c43,26.281) 43.184,26.457 43.237,26.4 ccw(c43.421,26.576) 43.26,26.379 ccw(c43.67,26.885) 43.275,26.367 ccw(c43.696,26.919) 43.696,26.225 ; 43.697,26.225 44.105,26.225 R7.2@44.422,25.908
NetR8_2: R8.2 U1.59 | length 3.6
  Top Layer w0.254: U1.59@41.084,27.213 42.701,27.213 ; 42.701,27.215 ccw(c42.701,27.706) 43.049,27.359 43.184,27.494 ; 43.185,27.494 cw(c43.553,27.126) 43.553,27.647 44.207,27.647 R8.2@44.422,27.432
NetR10_2: R10.2 U1.69 U2.4 | length 33.9
  Top Layer w0.254: U1.69@41.081,32.21 49.673,32.21 ccw(c49.673,32.575) 50.038,32.575 50.038,32.784 50.11,38.285 50.11,39.941 cw(c50.538,39.941) 50.538,40.369 52.053,40.369 ; 52.072,40.368 56.301,40.368 ; R10.2@57.49,43.418 57.46,43.448 56.777,43.448 ccw(c56.777,42.972) 56.301,42.972 56.301,40.368 ; U2.4@62.867,41.214 62.502,41.214 62.334,41.046 62.334,41.012 61.995,40.674 cw(c61.361,41.181) 61.359,40.368 56.301,40.368
NetR17_2: R17.2 U1.60 | length 3.8
  Top Layer w0.254: U1.60@41.081,27.71 42.201,27.71 ccw(c42.201,28.413) 42.683,27.902 ccw(c42.201,28.413) 42.697,27.916 43.612,28.831 cw(c43.865,28.577) 43.865,28.935 ; 43.865,28.939 44.405,28.939 R17.2@44.422,28.956
NetR18_1: R18.1 U1.47 U9.5 | length 34
  Top Layer w0.254: U1.47@37.901,21.53 37.9,21.529 37.9,18.474 ccw(c38.279,18.473) 38.329,18.097 cw(c38.361,17.845) 38.361,18.099 40.302,18.099 cw(c40.302,17.716) 40.685,17.716 40.685,13.822 ccw(c41.049,13.821) 41.049,13.457 49.533,13.457 cw(c49.533,12.87) 49.948,13.285 52.632,10.601 ccw(c53.084,11.053) 53.084,10.414 53.086,10.414 ; 53.086,10.412 U9.5@59.942,10.412 ; U9.5@59.944,10.414 60.246,10.414 60.414,10.582 R18.1@60.414,13.198
NetR19_2: R19.2 U1.77 U7.1 | length 13.2
  Top Layer w0.254: U1.77@38.901,36.89 38.914,36.903 U1.77@38.914,37.665 ; U1.77@38.909,37.665 cw(c39.239,37.665) 38.914,37.722 cw(c39.239,37.665) 39.005,37.898 39.211,38.103 cw(c39.464,37.851) 39.464,38.208 39.494,38.208 ; 39.494,38.209 40.07,38.209 v1(40.125,38.264) ; U7.1@42.159,44.915 42.159,44.558 U7.1@42.337,44.38 ; R19.2@43.497,44.38 R19.2@43.681,44.196
  Top Layer w0.508: v1(40.149,41.963) 41.485,41.963 ccw(c41.485,42.718) 42.24,42.718 42.24,44.437 42.291,44.488 42.291,44.915 U7.1@42.291,45.288 ; U7.1@42.337,44.38 R19.2@43.497,44.38
  Bottom Layer w0.381: v1@40.148,38.193 40.137,38.205 40.137,41.951 v1(40.149,41.963)
NetR21_1: R21.1 SW2.1 U6.9 | length 22
  Top Layer w0.254: 62.929,12.129 62.484,11.684 ccw(c62.953,11.215) 62.29,11.215 62.29,3.355 ccw(c62.635,3.355) 62.635,3.01 68.316,3.01 68.347,3.041 SW2.1@70.859,3.041 ; 62.932,12.126 ccw(c62.402,12.656) 62.986,12.186 ccw(c62.402,12.656) 63.152,12.656 U6.9@63.152,16.266
NetR24_1: R24.1 U1.46 U9.6 | length 40.1
  Top Layer w0.254: U1.46@37.401,21.53 37.407,21.524 37.407,18.188 37.407,18.186 ccw(c37.948,18.186) 37.971,17.645 cw(c37.98,17.391) 37.98,17.645 39.709,17.645 cw(c39.709,17.236) 40.118,17.236 40.118,13.424 ccw(c40.533,13.424) 40.533,13.009 49.276,13.009 cw(c49.276,12.634) 49.505,12.931 cw(c49.276,12.634) 49.541,12.899 ; 49.539,12.897 52.417,10.019 ccw(c52.69,10.293) 52.691,9.906 56.515,9.906 cw(c56.515,9.586) 56.835,9.586 ; 56.84,9.586 56.84,9.131 ; R24.1@59.182,3.528 59.151,3.559 57.147,3.559 cw(c57.147,3.866) 56.84,3.866 56.84,9.131 ; U9.6@59.931,9.131 56.84,9.131
NetR25_2: R25.2 U1.53 | length 8.2
  Top Layer w0.254: U1.53@41.081,24.21 46.98,24.21 cw(c46.981,23.158) 47.792,23.828 47.8,23.82 48.377,23.243 48.397,23.243 48.74,22.9 R25.2@48.74,22.88
NetR26_2: R26.2 U1.54 | length 7.7
  Top Layer w0.254: U1.54@41.081,24.71 R26.2@48.768,24.71
NetU1_78: U1.78 U7.6 | length 3.7
  Top Layer w0.254: U1.78@38.405,36.894 38.405,37.776 cw(c38.846,37.776) 38.494,38.043 cw(c38.846,37.776) 38.534,38.088 ; 38.537,38.085 39.53,39.078 39.573,39.078 39.751,39.256 U7.6@39.751,40.056
NetU1_79: U1.79 U7.5 | length 3.4
  Top Layer w0.254: U1.79@37.899,36.892 37.899,38.353 ccw(c37.645,38.353) 37.899,38.365 cw(c38.532,38.396) 38.084,38.845 38.303,39.064 38.303,39.878 U7.5@38.481,40.056
NetU1_80: U1.80 U7.2 | length 10.5
  Top Layer w0.254: U1.80@37.4,36.891 37.4,41.369 cw(c37.794,41.369) 37.794,41.763 38.529,41.763 ccw(c38.53,42.613) 39.132,42.012 40.817,43.697 ; 40.815,43.699 ccw(c40.402,44.112) 40.986,44.112 40.986,45.253 U7.2@41.021,45.288
NetU1_81: U1.81 U8.4 | length 26.7
  Top Layer w0.254: U1.81@36.901,36.896 36.901,37.543 36.901,45.522 ; 36.901,45.523 cw(c37.815,45.523) 37.169,46.17 39.399,48.4 cw(c40.115,47.687) 40.048,48.696 cw(c40.064,48.442) 40.064,48.696 48.273,48.696 ccw(c48.273,49.278) 48.854,49.278 48.854,50.524 cw(c49.49,50.524) 49.49,51.16 51.539,51.16 U8.4@51.56,51.181
NetU1_82: U1.82 U8.1 | length 30.1
  Top Layer w0.254: U1.82@36.401,37.48 36.401,45.864 ; 36.401,45.865 cw(c37.236,45.865) 36.646,46.456 39,48.809 cw(c40.123,47.69) 40.123,49.276 47.373,49.276 ccw(c47.373,50.115) 48.213,50.115 48.213,54.187 cw(c49.009,54.187) 49.009,54.983 U8.1@51.552,54.983
NetU9_1: U9.1 Y2.2 | length 3
  Top Layer w0.381: U9.1@64.894,6.604 65.48,6.604 65.584,6.499 65.584,4.5 Y2.2@65.766,4.318
NetU9_2: U9.2 Y2.1 | length 5.1
  Top Layer w0.381: 63.148,7.29 63.148,7.383 cw(c63.628,7.383) 63.153,7.45 cw(c63.628,7.383) 63.628,7.862 U9.2@64.882,7.862 ; 63.153,7.29 63.153,4.431 Y2.1@63.266,4.318
VCC_9-36V: U3.1 U4.1 U5.1 | length 28.1
  Top Layer w0.508: 3.298,20.57 4.327,19.542 4.436,19.542 U3.1@5.004,18.974 ; 3.302,20.574 cw(c4.528,21.8) 2.794,21.8 2.794,25.781 ; U5.1@5.075,42.418 5.075,42.377 4.37,41.672 4.329,41.672 3.3,40.642 ccw(c4.52,39.422) 2.794,39.422 2.794,25.781 ; U4.1@5.588,25.908 5.461,25.781 2.794,25.781
pads on no net: BT1. IDC2.3 U1.15 U1.16 U1.17 U1.18 U1.22 U1.23 U1.24 U1.25 U1.28 U1.61 U1.62 U1.66 U1.67 U1.68 U6.4 U6.5 U6.6 U6.7 U6.8 U6.17 U6.18 U6.19 U6.20 U6.21 U6.22 U6.24 U6.26 U6.29 U6.30 U6.31 U6.32 U6.33 U6.36 U6.37 U8.5 U8.8 U9.7

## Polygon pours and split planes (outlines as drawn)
GND on Bottom Layer "1" (solid, pour order 0): 1,57 89,57 89,1 1,1

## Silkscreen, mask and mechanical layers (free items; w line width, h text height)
Top Overlay:
  text "GND" at 72.136,52.832 h1.27
  text "ESP/EN" at 69.088,46.99 h1.27
  text "BOOT" at 73.614,46.961 h1.27
  text "H60R/ON" at 81.971,46.554 h1.27
  text "3V3" at 49.53,44.196 h1.27 r90
  text "L60R/ON" at 82.042,41.148 h1.27
  text "GND" at 49.53,40.894 h1.27 r90
  text "GND" at 51.054,39.37 h1.27
  text "BOOT" at 53.848,39.37 h1.27
  text "RX" at 57.404,39.37 h1.27
  text "TX" at 59.944,39.37 h1.27
  text "EN" at 62.484,39.37 h1.27
  text "3V3" at 65.024,39.37 h1.27
  text "RX2" at 68.834,39.37 h1.27
  text "TX2" at 71.374,39.37 h1.27
  text "GND" at 73.914,39.37 h1.27
  text "IO" at 49.53,39.116 h1.27 r90
  text "5V0" at 1.524,38.608 h1.52 r90
  text "CLK" at 49.53,35.814 h1.27 r90
  text "GND" at 1.448,29.185 h1.27 r90
  text "GND" at 77.47,26.924 h1.27 r90
  text "3V3" at 77.47,24.384 h1.27 r90
  text "+9-35V" at 1.372,23.571 h1.27 r90
  text "TMS" at 77.47,21.59 h1.27 r90
  text "RESET" at 14.604,21.316 h1.27
  text "RX5" at 47.779,19.775 h1.27 r90
  text "CLK" at 77.47,19.05 h1.27 r90
  text "CAN/H" at 89.662,17.78 h1.27 r90
  text "TX5" at 47.788,17.28 h1.27 r90
  text "TDO" at 77.47,16.256 h1.27 r90
  text "3V3" at 1.524,14.986 h1.52 r90
  text "GND" at 47.797,14.626 h1.27 r90
  text "Проект \"Хантер\"." at 23.368,14.478 h2.03
  text "TDI" at 77.47,13.97 h1.27 r90
  text "CAN/L" at 89.662,12.7 h1.27 r90
  text "Модуль \"Умник\" 31.08.23" at 19.304,12.446 h2.03
  text "+" at 74.542,12.305 h2.03 r90
  text "Мищук А.Л." at 78.232,9.652 h2.03
  text "-" at 73.515,7.331 h2.54 r90
  text "Лучшее из двух миров :: energy4all.ru" at 27.417,0.688 h2.29
Mechanical 2:
  the board outline again, w0.254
